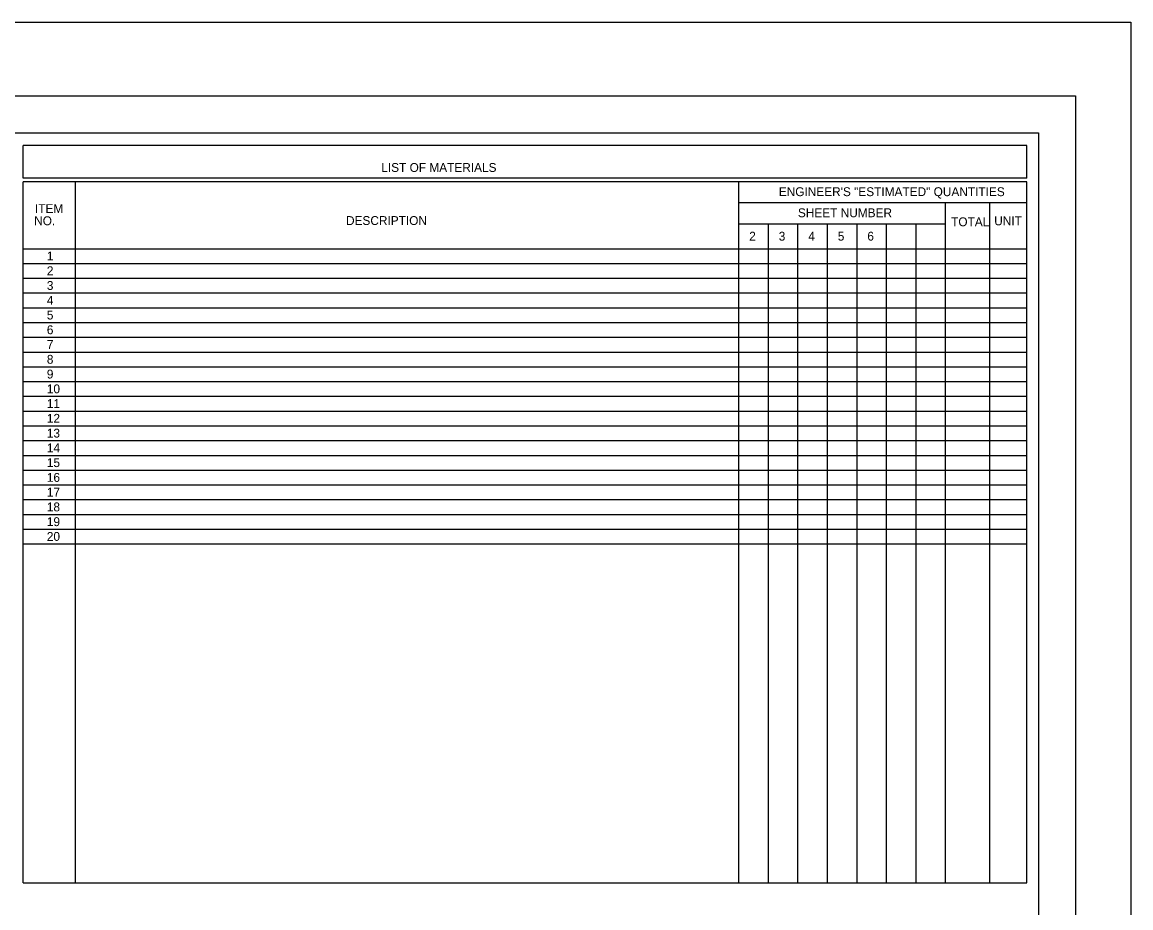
# Model space of a CAD drawing. Extents: x 837 to 1117, y 1316 to 1424.
# Drawn here: x 862.75 to 877.77, y 1410.24 to 1422.24 of the extents above; entities that cross this region are included whole.
import ezdxf

# ---------------------------------------------------------------- set-up
doc = ezdxf.new("R2010")
doc.units = 0
for name, color, linetype in [('0 (Construction)', 7, 'Continuous'), ('BASEMAP', 7, 'Continuous'), ('LLINES', 7, 'Continuous')]:
    doc.layers.add(name, color=color, linetype=linetype)

msp = doc.modelspace()

# ---------------------------------------------------------------- linework, layer by layer
at = {"layer": '0 (Construction)'}
msp.add_lwpolyline([(841.77, 1422.24), (877.77, 1422.24), (877.77, 1398.24), (841.77, 1398.24)], close=True, dxfattribs=at)
at = {"layer": 'BASEMAP'}
for p, q in [((843.02, 1421.24), (877.02, 1421.24)), ((877.02, 1421.24), (877.02, 1399.24)), ((843.52, 1420.74), (876.52, 1420.74)), ((876.52, 1420.74), (876.52, 1399.74)), ((876.362, 1420.569), (862.767, 1420.569)), ((862.767, 1420.126), (862.767, 1420.569)), ((876.362, 1420.126), (876.362, 1420.569)), ((876.362, 1420.126), (862.767, 1420.126)), ((862.767, 1410.581), (862.767, 1420.078)), ((876.362, 1420.078), (862.767, 1420.078)), ((863.477, 1410.581), (863.477, 1420.078)), ((872.462, 1410.581), (872.462, 1420.078)), ((876.362, 1410.581), (876.362, 1420.078)), ((876.362, 1419.79), (872.462, 1419.79)), ((875.262, 1410.581), (875.262, 1419.79)), ((875.862, 1410.581), (875.862, 1419.79)), ((875.262, 1419.502), (872.462, 1419.502)), ((872.862, 1410.581), (872.862, 1419.502)), ((873.262, 1410.581), (873.262, 1419.502)), ((873.662, 1410.581), (873.662, 1419.502)), ((874.062, 1410.581), (874.062, 1419.502)), ((874.462, 1410.581), (874.462, 1419.502)), ((874.862, 1410.581), (874.862, 1419.502)), ((876.362, 1419.166), (862.767, 1419.166)), ((876.362, 1418.966), (862.767, 1418.966)), ((876.362, 1418.766), (862.767, 1418.766)), ((876.362, 1418.566), (862.767, 1418.566)), ((876.362, 1418.366), (862.767, 1418.366)), ((876.362, 1418.166), (862.767, 1418.166)), ((876.362, 1417.966), (862.767, 1417.966)), ((876.362, 1417.766), (862.767, 1417.766)), ((876.362, 1417.566), (862.767, 1417.566)), ((876.362, 1417.366), (862.767, 1417.366)), ((876.362, 1417.166), (862.767, 1417.166)), ((876.362, 1416.966), (862.767, 1416.966)), ((876.362, 1416.766), (862.767, 1416.766)), ((876.362, 1416.566), (862.767, 1416.566)), ((876.362, 1416.366), (862.767, 1416.366)), ((876.362, 1416.166), (862.767, 1416.166)), ((876.362, 1415.966), (862.767, 1415.966)), ((876.362, 1415.766), (862.767, 1415.766)), ((876.362, 1415.566), (862.767, 1415.566)), ((876.362, 1415.366), (862.767, 1415.366)), ((876.362, 1415.166), (862.767, 1415.166)), ((862.767, 1410.581), (876.362, 1410.581))]:
    msp.add_line(p, q, dxfattribs=at)

# ---------------------------------------------------------------- texts
at = {"layer": 'LLINES'}
for s, p in [('LIST OF MATERIALS', (867.618, 1420.211)), ('ENGINEER\'S "ESTIMATED" QUANTITIES', (873.002, 1419.883)), ('ITEM', (862.927, 1419.654)), ('SHEET NUMBER', (873.261, 1419.597)), (' NO.', (862.872, 1419.489)), ('DESCRIPTION', (867.14, 1419.492)), ('TOTAL', (875.336, 1419.475)), ('UNIT', (875.92, 1419.487)), ('2', (872.601, 1419.28)), ('3', (873.001, 1419.28)), ('4', (873.401, 1419.28)), ('5', (873.801, 1419.28)), ('6', (874.201, 1419.28)), ('1', (863.088, 1419.012)), ('2', (863.088, 1418.812)), ('3', (863.088, 1418.612)), ('4', (863.088, 1418.412)), ('5', (863.088, 1418.212)), ('6', (863.088, 1418.012)), ('7', (863.088, 1417.812)), ('8', (863.088, 1417.612)), ('9', (863.088, 1417.412)), ('10', (863.088, 1417.212)), ('11', (863.088, 1417.012)), ('12', (863.088, 1416.812)), ('13', (863.088, 1416.612)), ('14', (863.088, 1416.412)), ('15', (863.088, 1416.212)), ('16', (863.088, 1416.012)), ('17', (863.088, 1415.812)), ('18', (863.088, 1415.612)), ('19', (863.088, 1415.412)), ('20', (863.088, 1415.212))]:
    msp.add_text(s, height=0.12, dxfattribs=at).set_placement(p)

doc.saveas('drawing.dxf')
